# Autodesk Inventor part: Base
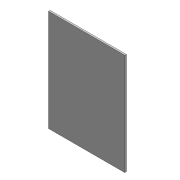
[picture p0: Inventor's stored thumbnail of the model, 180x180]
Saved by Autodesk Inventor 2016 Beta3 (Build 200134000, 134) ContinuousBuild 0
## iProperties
Created: 2016-03
Part Number: Base
Material: Generic
Document SubType Name: Modeling
Designer: Gaurav
Density: 1 g/cm^3
Appearance: Default
Author: Gaurav
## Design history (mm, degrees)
sketch "Sketch1"
  geometry: L1 (75, 100)-(-75, 100); L2 (-75, 100)-(-75, -100); L3 (-75, -100)-(75, -100); L4 (75, -100)-(75, 100); L5 (75, 100)-(-75, -100); L6 (-75, 100)-(75, -100); 1 further point
  constraints: 12 end point, 2 midpoint, 2 parallel, 1 horizontal, 1 perpendicular
  dimensions: "d0" = 150 distance of L3.end L2.end; "d1" = 200 distance of L2.end L1.end
extrude "Extrusion1" new body sketch "Sketch1" distance "d2" = 3; taper "d3" = 0 deg
sketch "Sketch2"
  geometry: C1 r 2.5 at (0, -45); C2 r 2.5 at (0, 45); 1 further point
  constraints: 2 centre point
  dimensions: "d4" = 5 diameter of C1; "d5" = 5 diameter of C2
extrude "Extrusion2" join sketch "Sketch2" distance "d6" = 10; taper "d7" = 0 deg
sketch "Sketch3"
  geometry: C1 r 2.5 at (0, -45) reference; C2 r 5 at (0, -45); C3 r 2.5 at (0, 45) reference; C4 r 5 at (0, 45); 1 further point
  constraints: 2 centre point, 2 coincident
  dimensions: "d8" = 10 diameter of C2; "d9" = 10 diameter of C4
extrude "Extrusion3" join sketch "Sketch3" distance "d10" = 2; taper "d11" = 0 deg
body "Solid1"
